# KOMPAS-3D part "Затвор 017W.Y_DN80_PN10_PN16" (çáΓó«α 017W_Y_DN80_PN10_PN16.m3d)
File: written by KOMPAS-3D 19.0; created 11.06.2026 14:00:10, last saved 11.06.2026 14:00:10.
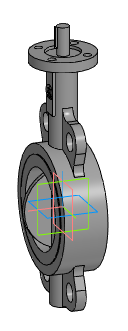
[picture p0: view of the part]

Document properties: Автор: Евгений; Полное имя файла: Z:\3.Личные\kachalov\001_3d для проектировщиков\x.x Тип 017W.Y(S) Затвор дисковый поворотный межфланцевый\_stp_Затвор 017W.Y_DN50-DN350\Затвор 017W_Y_DN80_PN10_PN16.m3d

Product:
- Part/product: Затвор 017W.Y_DN80_PN10_PN16

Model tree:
1. Операция без истории:1  (labels: Затвор 017W.Y_DN80_PN10_PN16)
